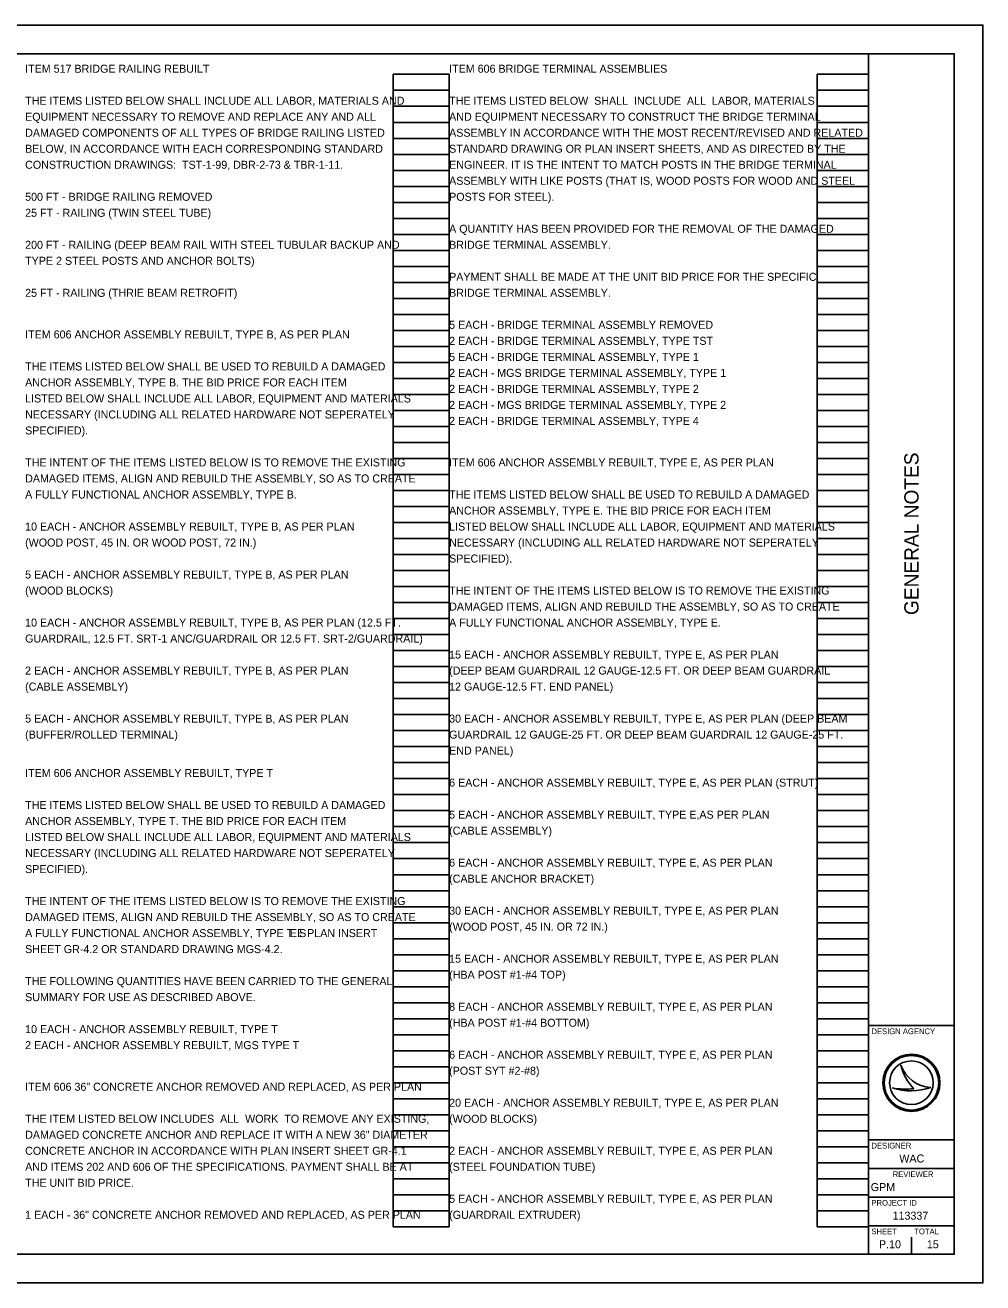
# Model space of a CAD drawing. Extents: x 0 to 34, y 0 to 22.
# Drawn here: x 17.24 to 34, y 0 to 22 of the extents above; entities that cross this region are included whole.
import ezdxf

# ---------------------------------------------------------------- set-up
doc = ezdxf.new("R2010")
doc.units = 0
for name, color, linetype in [('SH_Border', 7, 'Continuous'), ('SH_Cut_Line', 7, 'Continuous'), ('SH_Data', 7, 'Continuous'), ('SH_Text', 7, 'Continuous')]:
    doc.layers.add(name, color=color, linetype=linetype)

msp = doc.modelspace()

# ---------------------------------------------------------------- linework, layer by layer
at = {"layer": 'SH_Border'}
for p, q in [((32, 0.5), (32, 21.5)), ((32, 4.5), (33.5, 4.5)), ((32, 2.5), (33.5, 2.5)), ((32, 2), (33.5, 2)), ((32, 1.5), (33.5, 1.5)), ((32, 1), (33.5, 1))]:
    msp.add_line(p, q, dxfattribs=at)
msp.add_lwpolyline([(1.5, 21.5), (33.5, 21.5), (33.5, 0.5), (1.5, 0.5)], close=True, dxfattribs=at)
at = {"layer": 'SH_Cut_Line'}
msp.add_lwpolyline([(0, 0), (34, 0), (34, 22), (0, 22)], close=True, dxfattribs=at)
at = {"layer": 'SH_Data'}
for p, q in [((23.68, 0.98), (23.68, 21.14)), ((23.68, 21.14), (24.66, 21.14)), ((24.66, 0.98), (24.66, 21.14)), ((31.1, 0.98), (31.1, 21.14)), ((31.1, 21.14), (32, 21.14)), ((32, 0.98), (32, 21.14)), ((23.68, 20.86), (24.66, 20.86)), ((31.1, 20.86), (32, 20.86)), ((23.68, 20.58), (24.66, 20.58)), ((31.1, 20.58), (32, 20.58)), ((23.68, 20.3), (24.66, 20.3)), ((31.1, 20.3), (32, 20.3)), ((23.68, 20.02), (24.66, 20.02)), ((31.1, 20.02), (32, 20.02)), ((23.68, 19.74), (24.66, 19.74)), ((31.1, 19.74), (32, 19.74)), ((23.68, 19.46), (24.66, 19.46)), ((31.1, 19.46), (32, 19.46)), ((23.68, 19.18), (24.66, 19.18)), ((31.1, 19.18), (32, 19.18)), ((23.68, 18.9), (24.66, 18.9)), ((31.1, 18.9), (32, 18.9)), ((23.68, 18.62), (24.66, 18.62)), ((31.1, 18.62), (32, 18.62)), ((23.68, 18.34), (24.66, 18.34)), ((31.1, 18.34), (32, 18.34)), ((23.68, 18.06), (24.66, 18.06)), ((31.1, 18.06), (32, 18.06)), ((23.68, 17.78), (24.66, 17.78)), ((31.1, 17.78), (32, 17.78)), ((23.68, 17.5), (24.66, 17.5)), ((31.1, 17.5), (32, 17.5)), ((23.68, 17.22), (24.66, 17.22)), ((31.1, 17.22), (32, 17.22)), ((23.68, 16.94), (24.66, 16.94)), ((31.1, 16.94), (32, 16.94)), ((23.68, 16.66), (24.66, 16.66)), ((31.1, 16.66), (32, 16.66)), ((23.68, 16.38), (24.66, 16.38)), ((31.1, 16.38), (32, 16.38)), ((23.68, 16.1), (24.66, 16.1)), ((31.1, 16.1), (32, 16.1)), ((23.68, 15.82), (24.66, 15.82)), ((31.1, 15.82), (32, 15.82)), ((23.68, 15.54), (24.66, 15.54)), ((31.1, 15.54), (32, 15.54)), ((23.68, 15.26), (24.66, 15.26)), ((31.1, 15.26), (32, 15.26)), ((23.68, 14.98), (24.66, 14.98)), ((31.1, 14.98), (32, 14.98)), ((23.68, 14.7), (24.66, 14.7)), ((31.1, 14.7), (32, 14.7)), ((23.68, 14.42), (24.66, 14.42)), ((31.1, 14.42), (32, 14.42)), ((23.68, 14.14), (24.66, 14.14)), ((31.1, 14.14), (32, 14.14)), ((23.68, 13.86), (24.66, 13.86)), ((31.1, 13.86), (32, 13.86)), ((23.68, 13.58), (24.66, 13.58)), ((31.1, 13.58), (32, 13.58)), ((23.68, 13.3), (24.66, 13.3)), ((31.1, 13.3), (32, 13.3)), ((23.68, 13.02), (24.66, 13.02)), ((31.1, 13.02), (32, 13.02)), ((23.68, 12.74), (24.66, 12.74)), ((31.1, 12.74), (32, 12.74)), ((23.68, 12.46), (24.66, 12.46)), ((31.1, 12.46), (32, 12.46)), ((23.68, 12.18), (24.66, 12.18)), ((31.1, 12.18), (32, 12.18)), ((23.68, 11.9), (24.66, 11.9)), ((31.1, 11.9), (32, 11.9)), ((23.68, 11.62), (24.66, 11.62)), ((31.1, 11.62), (32, 11.62)), ((23.68, 11.34), (24.66, 11.34)), ((31.1, 11.34), (32, 11.34)), ((23.68, 11.06), (24.66, 11.06)), ((31.1, 11.06), (32, 11.06)), ((23.68, 10.78), (24.66, 10.78)), ((31.1, 10.78), (32, 10.78)), ((23.68, 10.5), (24.66, 10.5)), ((31.1, 10.5), (32, 10.5)), ((23.68, 10.22), (24.66, 10.22)), ((31.1, 10.22), (32, 10.22)), ((23.68, 9.94), (24.66, 9.94)), ((31.1, 9.94), (32, 9.94)), ((23.68, 9.66), (24.66, 9.66)), ((31.1, 9.66), (32, 9.66)), ((23.68, 9.38), (24.66, 9.38)), ((31.1, 9.38), (32, 9.38)), ((23.68, 9.1), (24.66, 9.1)), ((31.1, 9.1), (32, 9.1)), ((23.68, 8.82), (24.66, 8.82)), ((31.1, 8.82), (32, 8.82)), ((23.68, 8.54), (24.66, 8.54)), ((31.1, 8.54), (32, 8.54)), ((23.68, 8.26), (24.66, 8.26)), ((31.1, 8.26), (32, 8.26)), ((23.68, 7.98), (24.66, 7.98)), ((31.1, 7.98), (32, 7.98)), ((23.68, 7.7), (24.66, 7.7)), ((31.1, 7.7), (32, 7.7)), ((23.68, 7.42), (24.66, 7.42)), ((31.1, 7.42), (32, 7.42)), ((23.68, 7.14), (24.66, 7.14)), ((31.1, 7.14), (32, 7.14)), ((23.68, 6.86), (24.66, 6.86)), ((31.1, 6.86), (32, 6.86)), ((23.68, 6.58), (24.66, 6.58)), ((31.1, 6.58), (32, 6.58)), ((23.68, 6.3), (24.66, 6.3)), ((31.1, 6.3), (32, 6.3)), ((23.68, 6.02), (24.66, 6.02)), ((31.1, 6.02), (32, 6.02)), ((23.68, 5.74), (24.66, 5.74)), ((31.1, 5.74), (32, 5.74)), ((23.68, 5.46), (24.66, 5.46)), ((31.1, 5.46), (32, 5.46)), ((23.68, 5.18), (24.66, 5.18)), ((31.1, 5.18), (32, 5.18)), ((23.68, 4.9), (24.66, 4.9)), ((31.1, 4.9), (32, 4.9)), ((23.68, 4.62), (24.66, 4.62)), ((31.1, 4.62), (32, 4.62)), ((23.68, 4.34), (24.66, 4.34)), ((31.1, 4.34), (32, 4.34)), ((23.68, 4.06), (24.66, 4.06)), ((31.1, 4.06), (32, 4.06)), ((23.68, 3.78), (24.66, 3.78)), ((31.1, 3.78), (32, 3.78)), ((32.567, 3.81), (32.567, 3.81)), ((23.68, 3.5), (24.66, 3.5)), ((31.1, 3.5), (32, 3.5)), ((32.417, 3.41), (32.417, 3.41)), ((32.75, 3.5), (32.75, 3.5)), ((33.087, 3.419), (33.087, 3.419)), ((23.68, 3.22), (24.66, 3.22)), ((31.1, 3.22), (32, 3.22)), ((23.68, 2.94), (24.66, 2.94)), ((31.1, 2.94), (32, 2.94)), ((23.68, 2.66), (24.66, 2.66)), ((31.1, 2.66), (32, 2.66)), ((23.68, 2.38), (24.66, 2.38)), ((31.1, 2.38), (32, 2.38)), ((23.68, 2.1), (24.66, 2.1)), ((31.1, 2.1), (32, 2.1)), ((23.68, 1.82), (24.66, 1.82)), ((31.1, 1.82), (32, 1.82)), ((23.68, 1.54), (24.66, 1.54)), ((31.1, 1.54), (32, 1.54)), ((23.68, 1.26), (24.66, 1.26)), ((31.1, 1.26), (32, 1.26)), ((23.68, 0.98), (24.66, 0.98)), ((31.1, 0.98), (32, 0.98)), ((32.375, 0.675), (32.375, 0.675)), ((32.75, 0.5), (32.75, 0.8))]:
    msp.add_line(p, q, dxfattribs=at)
for radius in [0.5, 0.477, 0.477, 0.382]:
    msp.add_circle((32.75, 3.5), radius, dxfattribs=at)
for centre, radius, start, end in [((33.116, 3.998), 0.58, 198.9257, 198.9319), ((33.347, 3.97), 0.796, 191.6379, 191.6421), ((33.116, 3.998), 0.58, 198.9319, 267.1657), ((33.347, 3.97), 0.796, 191.6421, 226.0947), ((32.739, 4.37), 1.013, 251.4576, 290.0832), ((32.648, 4.654), 1.266, 259.4964, 259.4995), ((32.739, 4.37), 1.013, 251.4527, 251.4576), ((32.648, 4.654), 1.266, 259.4995, 276.6672)]:
    msp.add_arc(centre, radius, start, end, dxfattribs=at)

# ---------------------------------------------------------------- texts
msp.add_text('GENERAL NOTES', height=0.25, rotation=90, dxfattribs=at).set_placement((32.875, 11.682))
for s, height, p in [('DESIGN AGENCY', 0.1, (32.05, 4.35)), ('DESIGNER', 0.1, (32.05, 2.35)), ('WAC', 0.14, (32.538, 2.105)), ('REVIEWER', 0.1, (32.422, 1.85)), ('GPM', 0.14, (32.038, 1.605)), ('PROJECT ID', 0.1, (32.05, 1.35)), ('113337', 0.14, (32.42, 1.105)), ('SHEET', 0.1, (32.05, 0.85)), ('TOTAL', 0.1, (32.8, 0.85)), ('P.10', 0.14, (32.182, 0.605)), ('15', 0.14, (33.02, 0.605))]:
    msp.add_text(s, height=height, dxfattribs=at).set_placement(p)
at = {"layer": 'SH_Text'}
for s, p in [('ITEM 517 BRIDGE RAILING REBUILT', (17.24, 21.168)), ('ITEM 606 BRIDGE TERMINAL ASSEMBLIES', (24.66, 21.168)), ('THE ITEMS LISTED BELOW SHALL INCLUDE ALL LABOR, MATERIALS AND', (17.24, 20.608)), ('THE ITEMS LISTED BELOW  SHALL  INCLUDE  ALL  LABOR, MATERIALS', (24.66, 20.608)), ('EQUIPMENT NECESSARY TO REMOVE AND REPLACE ANY AND ALL', (17.24, 20.328)), ('AND EQUIPMENT NECESSARY TO CONSTRUCT THE BRIDGE TERMINAL', (24.66, 20.328)), ('DAMAGED COMPONENTS OF ALL TYPES OF BRIDGE RAILING LISTED', (17.24, 20.048)), ('ASSEMBLY IN ACCORDANCE WITH THE MOST RECENT/REVISED AND RELATED', (24.66, 20.048)), ('BELOW, IN ACCORDANCE WITH EACH CORRESPONDING STANDARD', (17.24, 19.768)), ('STANDARD DRAWING OR PLAN INSERT SHEETS, AND AS DIRECTED BY THE', (24.66, 19.768)), ('CONSTRUCTION DRAWINGS:  TST-1-99, DBR-2-73 & TBR-1-11.', (17.24, 19.488)), ('ENGINEER. IT IS THE INTENT TO MATCH POSTS IN THE BRIDGE TERMINAL', (24.66, 19.488)), ('ASSEMBLY WITH LIKE POSTS (THAT IS, WOOD POSTS FOR WOOD AND STEEL', (24.66, 19.208)), ('500 FT - BRIDGE RAILING REMOVED', (17.24, 18.928)), ('POSTS FOR STEEL).', (24.66, 18.928)), ('25 FT - RAILING (TWIN STEEL TUBE)', (17.24, 18.648)), ('A QUANTITY HAS BEEN PROVIDED FOR THE REMOVAL OF THE DAMAGED', (24.66, 18.368)), ('200 FT - RAILING (DEEP BEAM RAIL WITH STEEL TUBULAR BACKUP AND ', (17.24, 18.088)), ('BRIDGE TERMINAL ASSEMBLY.', (24.66, 18.088)), ('TYPE 2 STEEL POSTS AND ANCHOR BOLTS)', (17.24, 17.808)), ('PAYMENT SHALL BE MADE AT THE UNIT BID PRICE FOR THE SPECIFIC', (24.66, 17.528)), ('25 FT - RAILING (THRIE BEAM RETROFIT)', (17.24, 17.248)), ('BRIDGE TERMINAL ASSEMBLY.', (24.66, 17.248)), ('5 EACH - BRIDGE TERMINAL ASSEMBLY REMOVED', (24.66, 16.688)), ('ITEM 606 ANCHOR ASSEMBLY REBUILT, TYPE B, AS PER PLAN', (17.24, 16.52)), ('2 EACH - BRIDGE TERMINAL ASSEMBLY, TYPE TST', (24.66, 16.408)), ('THE ITEMS LISTED BELOW SHALL BE USED TO REBUILD A DAMAGED', (17.24, 15.96)), ('5 EACH - BRIDGE TERMINAL ASSEMBLY, TYPE 1', (24.66, 16.128)), ('2 EACH - MGS BRIDGE TERMINAL ASSEMBLY, TYPE 1', (24.66, 15.848)), ('ANCHOR ASSEMBLY, TYPE B. THE BID PRICE FOR EACH ITEM', (17.24, 15.68)), ('2 EACH - BRIDGE TERMINAL ASSEMBLY, TYPE 2', (24.66, 15.568)), ('LISTED BELOW SHALL INCLUDE ALL LABOR, EQUIPMENT AND MATERIALS', (17.24, 15.4)), ('2 EACH - MGS BRIDGE TERMINAL ASSEMBLY, TYPE 2', (24.66, 15.288)), ('NECESSARY (INCLUDING ALL RELATED HARDWARE NOT SEPERATELY', (17.24, 15.12)), ('SPECIFIED).', (17.24, 14.84)), ('2 EACH - BRIDGE TERMINAL ASSEMBLY, TYPE 4', (24.66, 15.008)), ('THE INTENT OF THE ITEMS LISTED BELOW IS TO REMOVE THE EXISTING', (17.24, 14.28)), ('ITEM 606 ANCHOR ASSEMBLY REBUILT, TYPE E, AS PER PLAN', (24.66, 14.28)), ('DAMAGED ITEMS, ALIGN AND REBUILD THE ASSEMBLY, SO AS TO CREATE', (17.24, 14)), ('A FULLY FUNCTIONAL ANCHOR ASSEMBLY, TYPE B. ', (17.24, 13.72)), ('THE ITEMS LISTED BELOW SHALL BE USED TO REBUILD A DAMAGED', (24.66, 13.72)), ('ANCHOR ASSEMBLY, TYPE E. THE BID PRICE FOR EACH ITEM', (24.66, 13.44)), ('10 EACH - ANCHOR ASSEMBLY REBUILT, TYPE B, AS PER PLAN', (17.24, 13.16)), ('LISTED BELOW SHALL INCLUDE ALL LABOR, EQUIPMENT AND MATERIALS', (24.66, 13.16)), ('(WOOD POST, 45 IN. OR WOOD POST, 72 IN.)', (17.24, 12.88)), ('NECESSARY (INCLUDING ALL RELATED HARDWARE NOT SEPERATELY', (24.66, 12.88)), ('SPECIFIED).', (24.66, 12.6)), ('5 EACH - ANCHOR ASSEMBLY REBUILT, TYPE B, AS PER PLAN', (17.24, 12.32)), ('(WOOD BLOCKS)', (17.24, 12.04)), ('THE INTENT OF THE ITEMS LISTED BELOW IS TO REMOVE THE EXISTING', (24.66, 12.04)), ('DAMAGED ITEMS, ALIGN AND REBUILD THE ASSEMBLY, SO AS TO CREATE', (24.66, 11.76)), ('10 EACH - ANCHOR ASSEMBLY REBUILT, TYPE B, AS PER PLAN (12.5 FT.', (17.24, 11.48)), ('A FULLY FUNCTIONAL ANCHOR ASSEMBLY, TYPE E.', (24.66, 11.48)), ('GUARDRAIL, 12.5 FT. SRT-1 ANC/GUARDRAIL OR 12.5 FT. SRT-2/GUARDRAIL)', (17.24, 11.2)), ('15 EACH - ANCHOR ASSEMBLY REBUILT, TYPE E, AS PER PLAN', (24.66, 10.92)), ('2 EACH - ANCHOR ASSEMBLY REBUILT, TYPE B, AS PER PLAN', (17.24, 10.64)), ('(DEEP BEAM GUARDRAIL 12 GAUGE-12.5 FT. OR DEEP BEAM GUARDRAIL', (24.66, 10.64)), ('(CABLE ASSEMBLY)', (17.24, 10.36)), ('12 GAUGE-12.5 FT. END PANEL)', (24.66, 10.36)), ('5 EACH - ANCHOR ASSEMBLY REBUILT, TYPE B, AS PER PLAN', (17.24, 9.8)), ('30 EACH - ANCHOR ASSEMBLY REBUILT, TYPE E, AS PER PLAN (DEEP BEAM', (24.66, 9.8)), ('(BUFFER/ROLLED TERMINAL)', (17.24, 9.52)), ('GUARDRAIL 12 GAUGE-25 FT. OR DEEP BEAM GUARDRAIL 12 GAUGE-25 FT.', (24.66, 9.52)), ('END PANEL)', (24.66, 9.24)), ('ITEM 606 ANCHOR ASSEMBLY REBUILT, TYPE T', (17.24, 8.848)), ('6 EACH - ANCHOR ASSEMBLY REBUILT, TYPE E, AS PER PLAN (STRUT)', (24.66, 8.68)), ('THE ITEMS LISTED BELOW SHALL BE USED TO REBUILD A DAMAGED', (17.24, 8.288)), ('ANCHOR ASSEMBLY, TYPE T. THE BID PRICE FOR EACH ITEM', (17.24, 8.008)), ('5 EACH - ANCHOR ASSEMBLY REBUILT, TYPE E,AS PER PLAN', (24.66, 8.12)), ('(CABLE ASSEMBLY)', (24.66, 7.84)), ('LISTED BELOW SHALL INCLUDE ALL LABOR, EQUIPMENT AND MATERIALS', (17.24, 7.728)), ('NECESSARY (INCLUDING ALL RELATED HARDWARE NOT SEPERATELY', (17.24, 7.448)), ('SPECIFIED).', (17.24, 7.168)), ('6 EACH - ANCHOR ASSEMBLY REBUILT, TYPE E, AS PER PLAN', (24.66, 7.28)), ('(CABLE ANCHOR BRACKET)', (24.66, 7)), ('THE INTENT OF THE ITEMS LISTED BELOW IS TO REMOVE THE EXISTING', (17.24, 6.608)), ('DAMAGED ITEMS, ALIGN AND REBUILD THE ASSEMBLY, SO AS TO CREATE', (17.24, 6.328)), ('30 EACH - ANCHOR ASSEMBLY REBUILT, TYPE E, AS PER PLAN', (24.66, 6.44)), ('A FULLY FUNCTIONAL ANCHOR ASSEMBLY, TYPE T. S', (17.24, 6.048)), ('EE PLAN INSERT', (21.873, 6.048)), ('(WOOD POST, 45 IN. OR 72 IN.)', (24.66, 6.16)), ('SHEET GR-4.2 OR STANDARD DRAWING MGS-4.2.', (17.24, 5.768)), ('15 EACH - ANCHOR ASSEMBLY REBUILT, TYPE E, AS PER PLAN', (24.66, 5.6)), ('THE FOLLOWING QUANTITIES HAVE BEEN CARRIED TO THE GENERAL', (17.24, 5.208)), ('(HBA POST #1-#4 TOP)', (24.66, 5.32)), ('SUMMARY FOR USE AS DESCRIBED ABOVE.  ', (17.24, 4.928)), ('8 EACH - ANCHOR ASSEMBLY REBUILT, TYPE E, AS PER PLAN', (24.66, 4.76)), ('(HBA POST #1-#4 BOTTOM)', (24.66, 4.48)), ('10 EACH - ANCHOR ASSEMBLY REBUILT, TYPE T ', (17.24, 4.368)), ('2 EACH - ANCHOR ASSEMBLY REBUILT, MGS TYPE T', (17.24, 4.088)), ('6 EACH - ANCHOR ASSEMBLY REBUILT, TYPE E, AS PER PLAN', (24.66, 3.92)), ('(POST SYT #2-#8)', (24.66, 3.64)), ('ITEM 606 36" CONCRETE ANCHOR REMOVED AND REPLACED, AS PER PLAN', (17.24, 3.36)), ('20 EACH - ANCHOR ASSEMBLY REBUILT, TYPE E, AS PER PLAN', (24.66, 3.08)), ('THE ITEM LISTED BELOW INCLUDES  ALL  WORK  TO REMOVE ANY EXISTING,', (17.24, 2.8)), ('(WOOD BLOCKS)', (24.66, 2.8)), ('DAMAGED CONCRETE ANCHOR AND REPLACE IT WITH A NEW 36" DIAMETER', (17.24, 2.52)), ('CONCRETE ANCHOR IN ACCORDANCE WITH PLAN INSERT SHEET GR-4.1', (17.24, 2.24)), ('2 EACH - ANCHOR ASSEMBLY REBUILT, TYPE E, AS PER PLAN', (24.66, 2.24)), ('AND ITEMS 202 AND 606 OF THE SPECIFICATIONS. PAYMENT SHALL BE AT', (17.24, 1.96)), ('(STEEL FOUNDATION TUBE)', (24.66, 1.96)), ('THE UNIT BID PRICE.', (17.24, 1.68)), ('5 EACH - ANCHOR ASSEMBLY REBUILT, TYPE E, AS PER PLAN', (24.66, 1.4)), ('1 EACH - 36" CONCRETE ANCHOR REMOVED AND REPLACED, AS PER PLAN', (17.24, 1.12)), ('(GUARDRAIL EXTRUDER)', (24.66, 1.12))]:
    msp.add_text(s, height=0.14, dxfattribs=at).set_placement(p)

doc.saveas('drawing.dxf')
